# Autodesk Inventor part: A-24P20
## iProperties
Author: Administrator
Shininess: 21.0
PropertySet Name: _Private Model Information
Length Units: 11272
Angle Units: 11286
Time Units: 11279
Mass Units: 11290
Length Display Precision: 3
Angle Display Precision: 2
Compacted: True
Created: 2001-03
Part Number: A-24P20
Material: Steel, Mild
Document SubType Name: Sheet Metal
Designer: Administrator
Control State: 0
Master: False
Checked Out: False
PropertySet Name: Design Tracking Control
Density: 0.0
Volumn: 0.0
Area: 0.0
PropertySet Name: Model Information
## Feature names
1. TallHoles [Extrusion]
2. WideHoles [Extrusion]
3. LTCorner
4. LBCorner
5. RTCorner
6. RBCorner
7. Plate1
8. Plate2
9. Bend1
10. Plate3
11. Bend2
12. Plate4
13. Bend3
14. Plate5
15. Bend4
